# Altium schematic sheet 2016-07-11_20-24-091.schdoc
size 339 x 185 mm; SheetNumber: 1; SheetTotal: 1
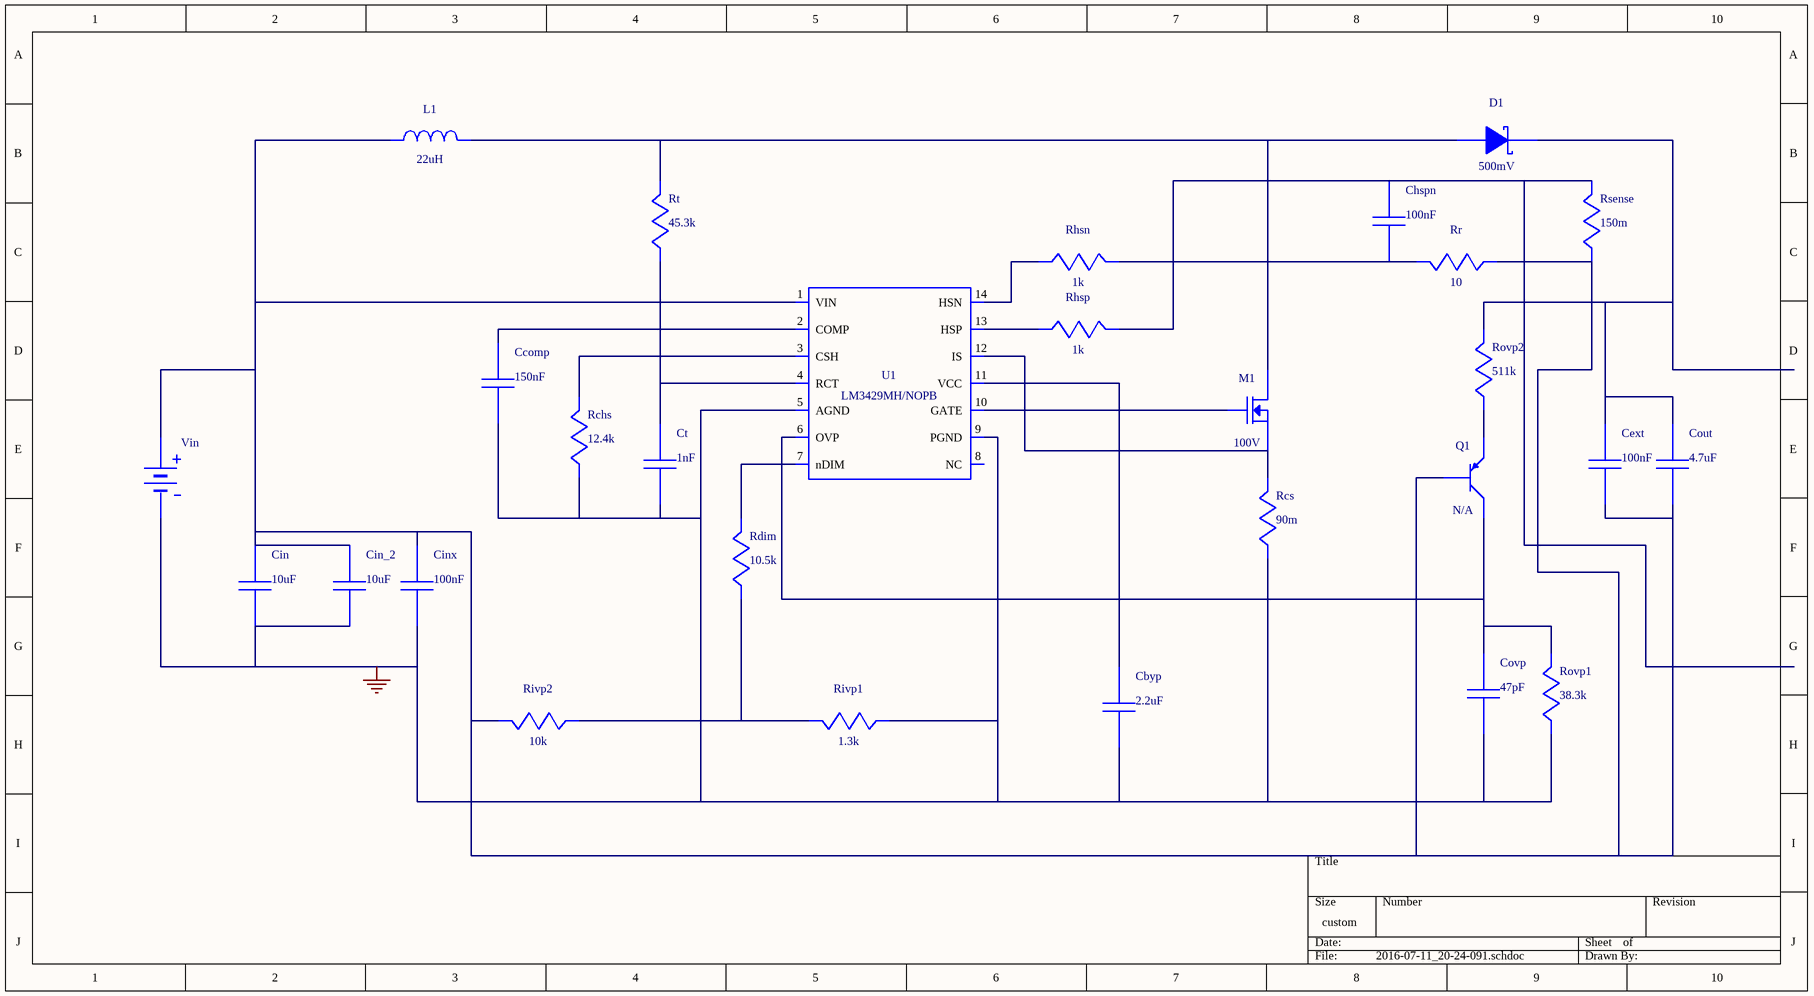
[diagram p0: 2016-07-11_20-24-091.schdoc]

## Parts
Cbyp  value 2.2uF  (hidden comment: EMK212B7225KG-T)
Ccomp  value 150nF  (hidden comment: GRM155R60J154KE01D)
Cext  value 100nF  (hidden comment: 08053C104KAT2A)
Chspn  value 100nF  (hidden comment: GRM21BR71E104KA01L)
Cin  value 10uF  (hidden comment: GRM31CR61E106KA12L)
Cin_2  value 10uF  (hidden comment: GRM31CR61E106KA12L)
Cinx  value 100nF  (hidden comment: C0603C104K5RACTU)
Cout  value 4.7uF  (hidden comment: GRM31CR71H475KA12L)
Covp  value 47pF  (hidden comment: C0805C470K5GACTU)
Ct  value 1nF  (hidden comment: CL21C102JBCNFNC)
D1  value 500mV  (hidden comment: B340A-13-F)
L1  value 22uH  (hidden comment: SDR1105-220ML)
M1  value 100V  (hidden comment: CSD16323Q3)
Q1  MMBT3906-7-F  (value not drawn)
Rchs  value 12.4k  (hidden comment: CRCW040212K4FKED)
Rcs  value 90m  (hidden comment: CRM0805-FW-R090ELF)
Rdim  value 10.5k  (hidden comment: CRCW040210K5FKED)
Rhsn  value 1k  (hidden comment: CRCW04021K00FKED)
Rhsp  value 1k  (hidden comment: CRCW04021K00FKED)
Rivp1  value 1.3k  (hidden comment: CRCW04021K30FKED)
Rivp2  value 10k  (hidden comment: CRCW040210K0FKED)
Rovp1  value 38.3k  (hidden comment: CRCW040238K3FKED)
Rovp2  value 511k  (hidden comment: CRCW0402511KFKED)
Rr  value 10  (hidden comment: CRCW040210R0FKED)
Rsense  value 150m  (hidden comment: ERJ-3RSFR15V)
Rt  value 45.3k  (hidden comment: CRCW040245K3FKED)
U1  LM3429MH  (value not drawn)
Vin  WB_BATTERY  (value not drawn)

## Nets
0: Cbyp.2 Ccomp.2 Cin.2 Cin_2.2 Cinx.2 Covp.2 Ct.2 Rchs.2 Rcs.2 Rivp1.2 Rovp1.2 U1.5(AGND) U1.9(PGND) U1.15(DAP) Vin.2(-)
NetCbyp_1: Cbyp.1 U1.11(VCC)
NetCcomp_1: Ccomp.1 U1.2(COMP)
NetCext_1: Cext.1 Cout.1 D1.1(K) Rovp2.1
NetCext_2: Cext.2 Cin.1 Cin_2.1 Cinx.1 Cout.2 L1.1 Q1.1(Base) Rivp2.1 Rr.2 Rsense.2 U1.1(VIN) Vin.1(+)
NetChspn_1: Chspn.1 Rhsp.1 Rsense.1
NetChspn_2: Chspn.2 Rhsn.1 Rr.1
NetCovp_1: Covp.1 Q1.3(Collector) Rovp1.1 U1.6(OVP)
NetCt_1: Ct.1 Rt.2 U1.4(RCT)
NetD1_2: D1.2(A) L1.2 M1.5(Drain) M1.6(Drain) M1.7(Drain) M1.8(Drain) M1.9(Drain) Rt.1
NetM1_1: M1.1(Source) M1.2(Source) M1.3(Source) Rcs.1 U1.12(IS)
NetM1_4: M1.4(Gate) U1.10(GATE)
NetQ1_2: Q1.2(Emitter) Rovp2.2
NetRchs_1: Rchs.1 U1.3(CSH)
NetRdim_1: Rdim.1 U1.7(nDIM)
NetRdim_2: Rdim.2 Rivp1.1 Rivp2.2
NetRhsn_2: Rhsn.2 U1.14(HSN)
NetRhsp_2: Rhsp.2 U1.13(HSP)

Not connected (* = marked no-connect by the designer): U1 8(NC)

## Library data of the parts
Cbyp = EMK212B7225KG-T: Manufacturer Name: Taiyo Yuden
Ccomp = GRM155R60J154KE01D: GRM155R60J154KE0; Manufacturer Name: MuRata
Cext = 08053C104KAT2A: Manufacturer Name: AVX
Chspn = GRM21BR71E104KA01L: GRM21BR71E104KA0; Manufacturer Name: MuRata
Cin Cin_2 = GRM31CR61E106KA12L: GRM31CR61E106KA1; Manufacturer Name: MuRata
Cinx = C0603C104K5RACTU: Manufacturer Name: Kemet
Cout = GRM31CR71H475KA12L: GRM31CR71H475KA1; Manufacturer Name: MuRata
Covp = C0805C470K5GACTU: Manufacturer Name: Kemet
Ct = CL21C102JBCNFNC: Manufacturer Name: Samsung Electro-Mechanics
D1 = B340A-13-F: Manufacturer Name: Diodes Inc.
L1 = SDR1105-220ML: Manufacturer Name: Bourns
M1 = CSD16323Q3: CSD19537Q3; Manufacturer Name: Texas Instruments
Q1 = MMBT3906-7-F: Manufacturer Name: Diodes Inc.
Rchs = CRCW040212K4FKED: Manufacturer Name: Vishay-Dale
Rcs = CRM0805-FW-R090ELF: CRM0805-FW-R090E; Manufacturer Name: Bourns
Rdim = CRCW040210K5FKED: Manufacturer Name: Vishay-Dale
Rhsn Rhsp = CRCW04021K00FKED: Manufacturer Name: Vishay-Dale
Rivp1 = CRCW04021K30FKED: Manufacturer Name: Vishay-Dale
Rivp2 = CRCW040210K0FKED: Manufacturer Name: Vishay-Dale
Rovp1 = CRCW040238K3FKED: Manufacturer Name: Vishay-Dale
Rovp2 = CRCW0402511KFKED: Manufacturer Name: Vishay-Dale
Rr = CRCW040210R0FKED: Manufacturer Name: Vishay-Dale
Rsense = ERJ-3RSFR15V: Manufacturer Name: Panasonic
Rt = CRCW040245K3FKED: Manufacturer Name: Vishay-Dale
U1 = LM3429MH: LM3429MH/NOPB; Manufacturer Name: Texas Instruments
